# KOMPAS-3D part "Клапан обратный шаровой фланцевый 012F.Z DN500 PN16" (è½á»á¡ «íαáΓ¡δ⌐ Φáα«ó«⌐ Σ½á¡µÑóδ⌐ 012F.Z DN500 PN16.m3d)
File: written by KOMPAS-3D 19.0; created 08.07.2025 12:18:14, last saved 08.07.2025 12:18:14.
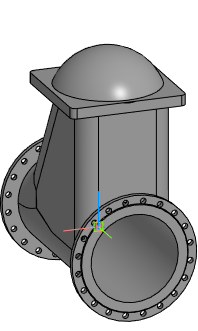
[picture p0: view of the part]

Document properties: Полное имя файла: E:\Dendor Работа Сачек\3D для проектировщиков\5.3 Тип 012F, 012F.Z Клапан обратный шаровой фланцевый\stp_Клапан обратный шаровой фланцевый 012F.Z PN10_16\Клапан обратный шаровой фланцевый 012F.Z DN500 PN16.m3d

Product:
- Part/product: Клапан обратный шаровой фланцевый 012F.Z DN500 PN16

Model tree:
1. Операция без истории:1  (labels: Клапан обратный шаровой фланцевый 012F.Z DN500 PN16)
